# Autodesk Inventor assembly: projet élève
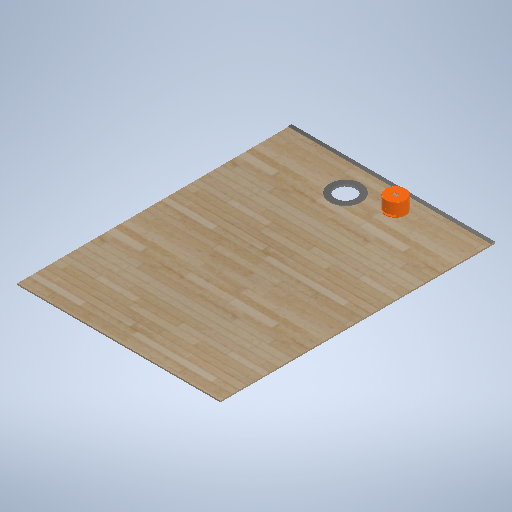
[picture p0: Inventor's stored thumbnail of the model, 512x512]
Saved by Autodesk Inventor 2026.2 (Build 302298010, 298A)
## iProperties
Created: 2026-09
Part Number: projet élève
Document SubType Name: Assembly
Designer: mel
Author: mel
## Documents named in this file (11)
- D:\travail\année 2026-2027\1 sti2d IT\poubelle à verre\projet élève.iam
- D:\travail\année 2026-2027\1 sti2d IT\poubelle à verre\facade.ipt
- D:\travail\année 2026-2027\1 sti2d IT\poubelle à verre\base.ipt
- D:\travail\année 2026-2027\1 sti2d IT\poubelle à verre\roulement 37 30 4.ipt
- D:\travail\année 2026-2027\1 sti2d IT\poubelle à verre\roulement 13 7 4.ipt
- D:\travail\année 2026-2027\1 sti2d IT\poubelle à verre\servo_model\servo_model\servo_model.ipt
- D:\travail\année 2026-2027\1 sti2d IT\poubelle à verre\couvercle supérieur.ipt
- D:\travail\année 2026-2027\1 sti2d IT\poubelle à verre\vma327-limit-switch-1.snapshot.2\VMA327_limit_switch\VMA327_limit_switch\VMA327_limit_switch.iam
- D:\travail\année 2026-2027\1 sti2d IT\poubelle à verre\affichage.iam
- D:\travail\année 2026-2027\1 sti2d IT\poubelle à verre\alimentation.iam
- D:\travail\année 2026-2027\1 sti2d IT\poubelle à verre\raspberry-pico-2-microcontroller-rp2350-1.snapshot.5\raspberry_pico_2\raspberry_pico_2\raspberry_pico_2.iam
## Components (11 placed, 10 different names)
1. facade:1 — Logement:1, Placage:1
2. base:1 — Logement:1, Placage:1, Logement:2, Logement:4, Angle:1, Affleurement:1, Placage:3, Affleurement:3, Placage:4, Placage:5, Affleurement:4, Affleurement:5, Placage:6, Placage:7, Affleurement:6
3. roulement 37 30 4:1 — Logement:2
4. roulement 13 7 4:1 — Logement:4
5. servo_model:1 — Angle:1
6. couvercle supérieur:1
7. VMA327_limit_switch:1 [sub-assembly] — Placage:3, Affleurement:3, Placage:4
8. VMA327_limit_switch:2 [sub-assembly] — Placage:5, Affleurement:4, Affleurement:5
9. affichage:1 [sub-assembly] — Logement:6, Placage:8, Affleurement:6, Placage:10, Affleurement:7
10. alimentation:1 [sub-assembly] — Placage:9, Placage:10, Placage:11
11. raspberry_pico_2:1 [sub-assembly] — Affleurement:7, Angle:2
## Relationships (22: Mate 10, Flush 6, Insert 4, Angle 2)
- Logement:1 [Insert]: facade:1 ↔ base:1
- Placage:1 [Mate]: facade:1 ↔ base:1
- Logement:2 [Insert]: base:1 ↔ roulement 37 30 4:1
- Logement:4 [Insert]: base:1 ↔ roulement 13 7 4:1
- Angle:1: base:1 ↔ servo_model:1
- Affleurement:1 [Flush]: base:1
- Placage:3 [Mate]: base:1 ↔ VMA327_limit_switch:1
- Affleurement:3 [Flush]: base:1 ↔ VMA327_limit_switch:1
- Placage:4 [Mate]: base:1 ↔ VMA327_limit_switch:1
- Placage:5 [Mate]: base:1 ↔ VMA327_limit_switch:2
- Affleurement:4 [Flush]: base:1 ↔ VMA327_limit_switch:2
- Affleurement:5 [Flush]: base:1 ↔ VMA327_limit_switch:2
- Logement:6 [Insert]: affichage:1
- Placage:6 [Mate]: base:1
- Placage:7 [Mate]: base:1
- Placage:8 [Mate]: affichage:1
- Affleurement:6 [Flush]: base:1 ↔ affichage:1
- Placage:9 [Mate]: alimentation:1
- Placage:10 [Mate]: affichage:1 ↔ alimentation:1
- Placage:11 [Mate]: alimentation:1
- Affleurement:7 [Flush]: affichage:1 ↔ raspberry_pico_2:1
- Angle:2: raspberry_pico_2:1
